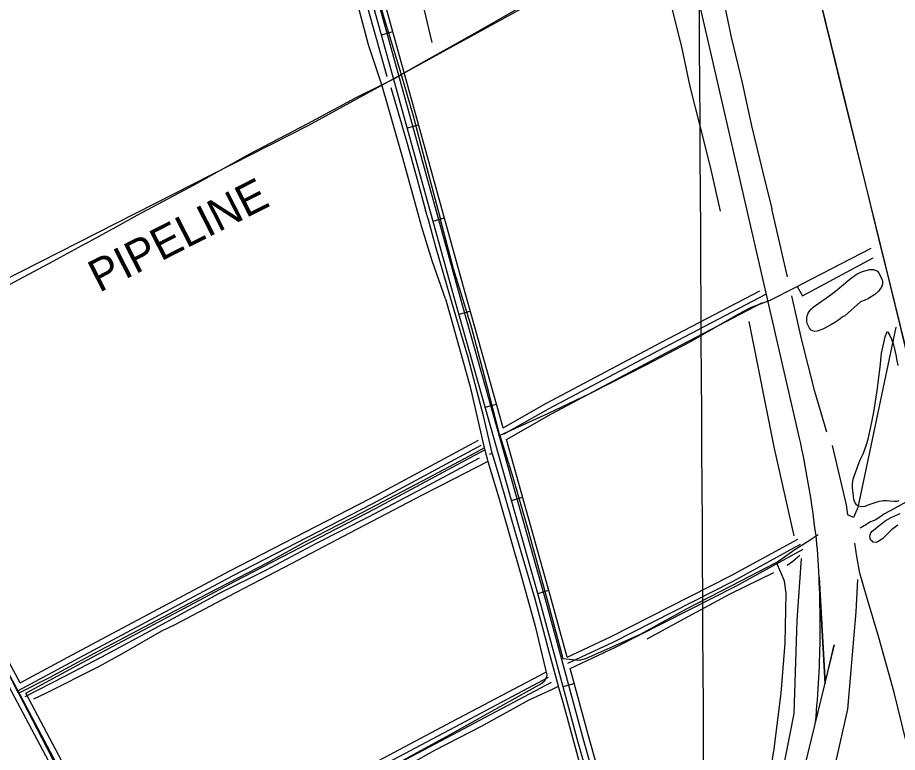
# Model space of a CAD drawing. Extents: x 3477039 to 3515015, y 546746 to 572297.
# Drawn here: x 3484689 to 3486964, y 566412 to 568313 of the extents above; entities that cross this region are included whole.
import ezdxf

# ---------------------------------------------------------------- set-up
doc = ezdxf.new("R2010")
doc.units = 0
for name, color, linetype in [('V-DTCH-CNTR', 7, 'Continuous'), ('V-GRID-MAJR', 7, 'Continuous'), ('V-RAIL-TRAK', 7, 'Continuous'), ('V-ROAD-CNTR', 7, 'Continuous'), ('V-SITE-VEGE', 7, 'Continuous'), ('V-TOPO-SHOR', 7, 'Continuous'), ('V-UTIL-IDEN', 7, 'Continuous'), ('V-UTIL-LINE', 7, 'Continuous')]:
    doc.layers.add(name, color=color, linetype=linetype)

msp = doc.modelspace()

# ---------------------------------------------------------------- linework, layer by layer
at = {"layer": 'V-DTCH-CNTR'}
for p, q in [((3485630.428, 568139.019), (3485661.847, 568154.6190000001)), ((3485816.227, 567662.634), (3485781.929, 567790.5750000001))]:
    msp.add_line(p, q, dxfattribs=at)
for points in [[(3485630.428, 568139.019), (3485596.423, 568241.759), (3485554.714, 568398.908), (3485510.833, 568547.155), (3485465.126, 568714.4890000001), (3485418.43, 568881.808), (3485377.3370000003, 569039.3), (3485345.455, 569145.878), (3485342.08, 569157.584), (3485309.318, 569271.225), (3485270.582, 569404.462), (3485231.296, 569541.164), (3485191.958, 569681.333), (3485155.059, 569824.017), (3485117.558, 569953.752), (3485115.2600000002, 569961.702), (3485074.7630000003, 570112.759), (3485029.551, 570280.101), (3485019.9982616, 570313.2061491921)], [(3485074.055938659, 570313.5285199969), (3485090.914, 570249.905), (3485131.861, 570101.831), (3485161.637, 569994.053), (3485163.362, 569987.812), (3485214.574, 569817.093), (3485249.191, 569693.705), (3485290.665, 569543.654), (3485338.531, 569364.952), (3485375.917, 569222.772), (3485386.995, 569183.481), (3485416.822, 569077.669), (3485459.789, 568927.147), (3485515.63, 568745.594), (3485552.932, 568608.863), (3485594.414, 568458.317), (3485635.325, 568312.72), (3485680.482, 568165.24)], [(3485661.847, 568154.6190000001), (3485680.482, 568165.24), (3485745.87, 568202.509), (3485872.674, 568272.87), (3486003.861, 568348.257), (3486130.663, 568418.618), (3486263.336, 568494.028), (3486359.705, 568545.082), (3486399.024, 568567.328)], [(3485680.482, 568165.24), (3485711.875, 568058.158), (3485746.679, 567922.875), (3485781.929, 567790.5750000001)], [(3484997.629, 567801.603), (3485145.231, 567880.2710000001), (3485289.344, 567959.879), (3485439.416, 568039.081), (3485563.8850000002, 568105.983), (3485630.428, 568139.019)], [(3485734.1580000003, 567770.506), (3485684.813, 567948.688), (3485647.077, 568081.448), (3485630.428, 568139.019)], [(3484865.629, 567728.803), (3484960.687, 567781.377), (3484997.629, 567801.603)], [(3485794.77, 567585.132), (3485760.532, 567683.513), (3485734.1580000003, 567770.506)], [(3484865.629, 567728.803), (3484779.767, 567681.897), (3484655.636, 567615.51), (3484576.63, 567572.188)], [(3486629.097, 567579.563), (3486704.293, 567617.232), (3486717.208, 567623.702), (3486895.447, 567716.277)], [(3486704.293, 567617.232), (3486718.156, 567593.502), (3486901.173, 567691.5210000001)], [(3485935.296, 567232.175), (3485907.881, 567339.763), (3485862.856, 567509.186), (3485816.227, 567662.634)], [(3485794.77, 567585.132), (3485808.174, 567539.475), (3485859.17, 567357.748), (3485895.257, 567200.38), (3485895.841, 567197.834), (3485902.583, 567171.409), (3485904.576, 567164.765), (3485932.898, 567070.375), (3485989.818, 566872.583), (3486026.796, 566738.537), (3486053.691, 566626.725), (3486056.8200000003, 566613.044), (3486055.79, 566605.528), (3486050.504, 566596.183), (3486042.906, 566590.158), (3485935.4020000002, 566530.283), (3485806.106, 566457.492), (3485636.112, 566364.491)], [(3486629.097, 567579.563), (3486585.616, 567562.6730000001), (3486551.066, 567545.21), (3486425.0670000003, 567472.852), (3486313.336, 567413.497), (3486169.452, 567340.41), (3486058.747, 567288.1), (3485935.296, 567232.175)], [(3485935.296, 567232.175), (3485969.2970000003, 567124.512), (3486008.145, 566989.503), (3486060.904, 566797.876), (3486096.455, 566662.438), (3486098.818, 566654.205)], [(3484691.134, 566566.0160000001), (3484771.589, 566606.456), (3484887.592, 566669.055), (3485031.974, 566744.485), (3485182.5270000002, 566824.547), (3485335.42, 566903.6410000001), (3485430.599, 566955.666), (3485581.123, 567033.378), (3485735.64, 567114.524), (3485858.737, 567180.33), (3485895.257, 567200.38)], [(3485904.576, 567164.765), (3485816.061, 567119.246), (3485735.122, 567077.873)], [(3485735.122, 567077.873), (3485586.9450000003, 566999.664), (3485564.704, 566988.637)], [(3485564.704, 566988.637), (3485410.377, 566907.68), (3485397.591, 566900.774)], [(3486440.965, 565449.836), (3486449.7120000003, 565473.252), (3486475.521, 565586.3200000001), (3486514.177, 565750.984), (3486548.8680000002, 565898.757), (3486570.333, 566041.986), (3486597.236, 566167.743), (3486626.123, 566302.414), (3486645.1410000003, 566421.773), (3486663.319, 566565.51), (3486673.802, 566695.226), (3486676.278, 566824.0970000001), (3486671.474, 566855.204), (3486665.5330000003, 566869.857), (3486660.0500000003, 566883.5650000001), (3486653.628, 566897.284), (3486650.879, 566903.432), (3486698.319, 566936.7390000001), (3486738.1380000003, 566962.138), (3486758.555, 566975.645)], [(3485397.591, 566900.774), (3485271.6720000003, 566835.002), (3485233.8000000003, 566815.225)], [(3486650.879, 566903.432), (3486533.017, 566842.74), (3486417.518, 566782.959), (3486298.6580000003, 566717.572), (3486157.2460000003, 566654.336), (3486141.202, 566650.2930000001), (3486098.818, 566654.205)], [(3484834.524, 566288.8910000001), (3484764.643, 566425.208), (3484691.971, 566564.384), (3484691.134, 566566.0160000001), (3484611.512, 566721.056), (3484567.772, 566801.081)], [(3485233.8000000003, 566815.225), (3485095.562, 566742.072), (3485060.554, 566725.553)], [(3485060.554, 566725.553), (3484957.759, 566666.0920000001), (3484898.1, 566633.87)], [(3484898.1, 566633.87), (3484761.3170000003, 566564.466), (3484729.6240000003, 566549.7880000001)]]:
    msp.add_lwpolyline(points, dxfattribs=at)
at = {"layer": 'V-GRID-MAJR'}
msp.add_spline([(3486543.572, 552138.781), (3486509.202, 558197.813), (3486474.821, 564258.778), (3486440.44, 570319.761), (3486440.429, 570321.677)], degree=3, dxfattribs=at)
at = {"layer": 'V-RAIL-TRAK'}
for points in [[(3486881.687, 567880.078), (3486858.483, 567973.17), (3486826.784, 568100.732), (3486792.089, 568242.517), (3486759.057, 568379.174), (3486722.7460000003, 568522.917), (3486691.759, 568655.642), (3486678.269, 568708.63), (3486655.467, 568798.197), (3486623.307, 568929.713), (3486591.198, 569058.061), (3486559.053, 569188.785), (3486527.278, 569321.102), (3486490.449, 569472.767), (3486455.801, 569611.382), (3486424.1210000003, 569737.752), (3486390.705, 569873.612), (3486356.4420000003, 570013.025), (3486328.9930000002, 570122.018), (3486300.178, 570242.487), (3486281.160594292, 570320.7270405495)], [(3487263.577, 566335.309), (3487241.75, 566421.7220000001), (3487220.502, 566507.544), (3487188.594, 566633.344), (3487156.2600000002, 566772.631), (3487122.085, 566904.907), (3487088.559, 567042.448), (3487057.2430000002, 567168.828), (3487026.544, 567297.545), (3486988.441, 567444.52), (3486969.466, 567524.453), (3486943.18, 567630.261), (3486915.786, 567741.357), (3486881.687, 567880.078)]]:
    msp.add_lwpolyline(points, dxfattribs=at)
at = {"layer": 'V-ROAD-CNTR'}
for p, q in [((3485629.8847021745, 568268.2404371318), (3485658.794644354, 568276.2514211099)), ((3485696.645568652, 568027.319918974), (3485725.555510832, 568035.330902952)), ((3485763.40643513, 567786.399400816), (3485792.317377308, 567794.410384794)), ((3485830.372301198, 567545.4738826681), (3485859.250243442, 567553.6008664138)), ((3485898.09616575, 567304.822363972), (3485926.974107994, 567312.94834772)), ((3485965.8200303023, 567064.169845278), (3485994.6979725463, 567072.2968290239)), ((3486033.543894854, 566823.5183265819), (3486062.421837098, 566831.645310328)), ((3486099.308763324, 566582.470808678), (3486128.261705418, 566590.3267929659))]:
    msp.add_line(p, q, dxfattribs=at)
for points in [[(3486463.731034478, 565338.246297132), (3486451.4930589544, 565363.68224626), (3486431.6880985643, 565404.7531641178), (3486138.49568495, 566438.053097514), (3486078.688804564, 566658.4646566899), (3486038.0198859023, 566807.610358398), (3485817.095327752, 567592.6537883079), (3485616.26172942, 568317.3983388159), (3485374.74221246, 569185.927601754), (3485127.3867071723, 570059.40785479), (3485058.2878453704, 570312.7433481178)], [(3486479.503002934, 565340.0612935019), (3486465.0070319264, 565370.1912332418), (3486445.764070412, 565410.0981534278), (3486152.9496560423, 566442.0640894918), (3486093.162775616, 566662.4016488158), (3486052.47585699, 566811.6153503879), (3485831.542298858, 567596.6887802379), (3485630.715700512, 568321.410330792), (3485389.184183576, 569189.9805936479), (3485141.8386782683, 570063.424846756), (3485072.7588164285, 570316.6903402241)], [(3485944.235073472, 567251.6144703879), (3485845.9892699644, 567600.7237721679), (3485645.1696716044, 568325.422322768), (3485403.6261546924, 569194.033585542), (3485156.2906493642, 570067.441838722), (3485088.280785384, 570316.7833400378)], [(3486710.89454015, 567225.4325227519), (3486478.8340042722, 568233.3885068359), (3486037.59588675, 570140.5416925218), (3485994.106973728, 570322.184329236)], [(3486710.89454015, 567225.4325227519), (3486478.8340042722, 568233.3885068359), (3486037.59588675, 570140.5416925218), (3485994.106973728, 570322.184329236)], [(3486281.2963993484, 570321.085331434), (3486969.8640222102, 567519.225935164), (3487264.1754335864, 566324.929323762)], [(3485261.6174387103, 565506.4209607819), (3485151.804658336, 565691.1675912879), (3485013.649934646, 565948.4260767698), (3484992.4669770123, 565993.858985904), (3484975.7580104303, 566037.2868990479), (3484914.272133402, 566147.826677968), (3484687.4565870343, 566575.922821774), (3484376.64920865, 567150.914671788), (3484166.0216299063, 567559.456854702), (3483812.5503368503, 568215.0615434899), (3483402.522156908, 568997.2639790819), (3483141.938678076, 569503.177967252), (3482987.7669864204, 569799.22837515)], [(3485245.3354712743, 565504.45696471), (3485138.743684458, 565683.783606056), (3485000.2339614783, 565941.7030902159), (3484978.6530046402, 565987.9899976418), (3484962.137037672, 566030.916911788), (3484901.089159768, 566140.6686922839), (3484674.2316134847, 566568.8448359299), (3484363.38423518, 567143.910685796), (3484152.752656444, 567552.4598686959), (3483799.3053633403, 568208.0195575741), (3483389.212183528, 568990.347992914), (3483387.0791877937, 568994.4889846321)], [(3484695.652570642, 566592.3057890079), (3484389.9141821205, 567157.9186577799), (3484179.290603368, 567566.453840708), (3483825.79531036, 568222.1035294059), (3483778.219405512, 568312.8623478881)], [(3485944.235073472, 567251.6144703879), (3486054.559852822, 567314.2903450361), (3486353.8572542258, 567472.86302789), (3486607.89974614, 567605.9337617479)], [(3485947.2430674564, 567236.0715014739), (3486061.777838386, 567301.139371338), (3486360.848240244, 567459.5920544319), (3486625.1147117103, 567598.0177775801)], [(3485952.6060567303, 567221.867529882), (3486068.99582395, 567287.9883976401), (3486367.839226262, 567446.3210809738), (3486614.8577322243, 567575.711822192)], [(3484689.437583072, 566572.183829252), (3484689.576582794, 566572.0018296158), (3484848.116265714, 566657.3266589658), (3485244.680472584, 566868.667236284), (3485607.140747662, 567056.1338613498), (3485887.758186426, 567206.9795596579)], [(3484695.652570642, 566592.3057890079), (3484841.0342798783, 566670.54963252), (3485237.7074865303, 566881.9482097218), (3485600.143761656, 567069.402834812), (3485880.632200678, 567220.1785332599)], [(3486109.696742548, 566658.7856560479), (3486066.9318280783, 566815.6203423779), (3485952.6060567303, 567221.867529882)], [(3486755.72445049, 566949.3560749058), (3486754.07445379, 566964.0010456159), (3486752.3464572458, 566978.6370163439), (3486750.537460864, 566993.262987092), (3486748.6494646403, 567007.87895786), (3486746.682468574, 567022.484928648), (3486744.6364726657, 567037.079899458), (3486742.5104769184, 567051.6638702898), (3486740.306481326, 567066.235841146), (3486738.022485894, 567080.794812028), (3486735.6594906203, 567095.3417829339), (3486733.218495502, 567109.8757538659), (3486730.697500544, 567124.396724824), (3486728.098505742, 567138.902695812), (3486725.420511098, 567153.395666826), (3486722.6635166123, 567167.872637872), (3486719.828522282, 567182.334608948), (3486716.91452811, 567196.7815800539), (3486713.9225340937, 567211.2125511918), (3486710.89454015, 567225.4325227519)], [(3486755.72445049, 566949.355074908), (3486754.07445379, 566964.0010456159), (3486752.3464572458, 566978.6370163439), (3486750.537460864, 566993.261987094), (3486748.6494646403, 567007.87895786), (3486746.682468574, 567022.484928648), (3486744.6364726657, 567037.079899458), (3486742.5104769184, 567051.6638702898), (3486740.306481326, 567066.235841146), (3486738.022485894, 567080.794812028), (3486735.658490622, 567095.3417829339), (3486733.218495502, 567109.8757538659), (3486730.697500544, 567124.3977248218), (3486728.098505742, 567138.902695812), (3486725.420511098, 567153.395666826), (3486722.6635166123, 567167.872637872), (3486719.828522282, 567182.334608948), (3486716.91452811, 567196.7815800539), (3486713.9225340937, 567211.2125511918), (3486710.89454015, 567225.4325227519)], [(3484709.774542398, 566565.837841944), (3484855.1982515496, 566644.103685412), (3485251.653458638, 566855.3862628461), (3485614.1377336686, 567042.864887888), (3485894.884172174, 567193.7805860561)], [(3486109.696742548, 566658.7856560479), (3486221.88051818, 566711.3525509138), (3486532.2698974, 566868.6212363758), (3486705.777550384, 566963.8690458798)], [(3486111.774738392, 566643.193687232), (3486228.454505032, 566697.867577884), (3486539.270883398, 566855.3532629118), (3486712.995535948, 566950.7200721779)], [(3486117.662726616, 566629.3867148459), (3486235.0284918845, 566684.3826048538), (3486546.2718693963, 566842.085289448), (3486720.213521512, 566937.571098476)], [(3486751.8894581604, 566490.236993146), (3486753.2404554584, 566504.628964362), (3486754.511452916, 566519.0279355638), (3486755.703450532, 566533.4339067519), (3486756.81444831, 566547.8458779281), (3486757.847446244, 566562.2648490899), (3486758.7994443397, 566576.6878202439), (3486759.6714425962, 566591.1167913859), (3486760.4644410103, 566605.550762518), (3486761.176439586, 566619.987733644), (3486761.8094383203, 566634.428704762), (3486762.362437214, 566648.8736758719), (3486762.83443627, 566663.3206469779), (3486763.227435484, 566677.770618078), (3486763.5404348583, 566692.222589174), (3486763.773434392, 566706.675560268), (3486763.9264340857, 566721.1305313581), (3486763.99943394, 566735.5855024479), (3486763.9924339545, 566750.040473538), (3486763.905434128, 566764.4954446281), (3486763.737434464, 566778.94941572), (3486763.490434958, 566793.4023868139), (3486763.163435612, 566807.8533579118), (3486762.756436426, 566822.3033290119), (3486762.2694374, 566836.750300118), (3486761.702438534, 566851.19427123), (3486761.055439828, 566865.6342423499), (3486776.527408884, 566590.3727928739), (3486759.522442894, 566894.5041846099), (3486758.6354446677, 566908.9321557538), (3486757.6694466, 566923.3551269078), (3486756.6234486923, 566937.772098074), (3486755.72445049, 566949.3560749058)], [(3486776.527408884, 566590.371792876), (3486759.522442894, 566894.5041846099), (3486758.6354446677, 566908.9321557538), (3486757.6694466, 566923.3551269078), (3486756.6234486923, 566937.772098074), (3486755.68445057, 566949.8760738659)], [(3486776.0264098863, 566588.2577971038), (3486800.333361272, 566690.8905918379), (3486723.6435146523, 566375.7222221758), (3486627.443707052, 565957.625058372), (3486536.9278880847, 565583.903805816), (3486489.22498349, 565381.343210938)], [(3484984.0569938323, 566053.224867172), (3485316.60232874, 566225.4405227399), (3485580.3998011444, 566368.7132361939), (3485812.748336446, 566492.1949892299), (3486054.201853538, 566619.9857336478)], [(3486474.624012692, 565384.781204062), (3486459.84004226, 565415.4431427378), (3486167.4036271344, 566446.0750814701), (3486117.662726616, 566629.3867148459)], [(3484976.894008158, 566034.333904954), (3484978.0260058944, 566033.208907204), (3485323.6313146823, 566212.188549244), (3485587.4987869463, 566355.4992626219), (3485819.77632239, 566478.943015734), (3486061.613838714, 566606.9367597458)], [(3484994.5549728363, 566024.876923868), (3485330.660300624, 566198.936575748), (3485594.597772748, 566342.2852890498), (3485826.8043083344, 566465.691042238), (3486069.0258238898, 566593.8877858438)], [(3484984.0569938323, 566053.224867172), (3484927.455107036, 566154.9846636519), (3484709.774542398, 566565.837841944)]]:
    msp.add_lwpolyline(points, dxfattribs=at)
at = {"layer": 'V-SITE-VEGE'}
msp.add_lwpolyline([(3486867.81, 567577.185), (3486827.318, 567541.669), (3486821.1520000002, 567537.845), (3486814.6, 567532.912), (3486801.698, 567524.3470000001), (3486791.794, 567518.152), (3486770.515, 567507.269), (3486756.163, 567501.503), (3486748.917, 567500.658), (3486740.793, 567503.908), (3486736.406, 567509.526), (3486731.517, 567519.97), (3486729.7460000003, 567527.042), (3486729.664, 567535.949), (3486730.284, 567541.323), (3486732.965, 567548.526), (3486735.245, 567552.951), (3486740.324, 567559.015), (3486745.759, 567563.591), (3486766.526, 567578.373), (3486777.179, 567585.299), (3486803.392, 567605.401), (3486813.6890000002, 567613.441), (3486840.676, 567636.504), (3486859.572, 567650.01), (3486872.995, 567655.603), (3486891.984, 567661.131), (3486901.819, 567661.204), (3486911.788, 567657.004), (3486915.9930000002, 567651.577), (3486921.799, 567640.561), (3486924.67, 567632.178), (3486924.752, 567623.458), (3486922.806, 567615.6900000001), (3486914.322, 567604.1), (3486905.327, 567596.414), (3486888.883, 567586.403), (3486877.875, 567581.15)], close=True, dxfattribs=at)
for points in [[(3486967.715, 567062.658), (3486961.762, 567061.059), (3486955.0810000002, 567060.9500000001), (3486944.151, 567062.377), (3486936.182, 567063.213), (3486927.832, 567063.125), (3486915.7490000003, 567061.04), (3486908.12, 567059.088), (3486897.133, 567055.508), (3486889.866, 567052.996), (3486879.055, 567048.6680000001), (3486871.994, 567047.638), (3486862.3680000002, 567049.424), (3486857.946, 567052.254), (3486854.115, 567057.681), (3486852.306, 567061.784), (3486851.247, 567066.248), (3486850.049, 567074.983), (3486848.843, 567082.79), (3486847.708, 567096.716), (3486847.823, 567106.549), (3486849.455, 567119.1460000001), (3486851.772, 567126.912), (3486858.487, 567145.756), (3486867.66, 567168.654), (3486874.7090000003, 567184.3420000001), (3486879.481, 567195.7880000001), (3486884.085, 567208.721), (3486887.96, 567222.777), (3486897.19, 567266.2660000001), (3486903.305, 567297.365), (3486911.755, 567353.48), (3486914.801, 567375.894), (3486918.71, 567408.502), (3486922.659, 567444.819), (3486932.059, 567487.008), (3486933.602, 567492.001), (3486935.127, 567495.507), (3486936.4790000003, 567499.9450000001), (3486938.509, 567499.179), (3486944.341, 567490.205), (3486948.501, 567481.064), (3486953.34, 567466.5380000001), (3486955.998, 567455.931), (3486959.345, 567440.678), (3486961.2600000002, 567429.895), (3486964.768, 567412.6)], [(3486964.94, 566999.797), (3486958.399, 566995.977), (3486948.29, 566988.117), (3486931.58, 566971.246), (3486925.012, 566964.827), (3486914.166, 566957.534), (3486908.389, 566955.376), (3486901.348, 566956.201), (3486899.693, 566957.334), (3486895.1010000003, 566961.468), (3486893.291, 566965.2000000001), (3486892.615, 566970.959), (3486892.846, 566974.852), (3486895.326, 566980.574), (3486898.5270000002, 566984.6190000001), (3486905.8370000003, 566990.843), (3486912.569, 566995.402), (3486923.622, 567004.5480000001), (3486931.859, 567010.944), (3486947.176, 567019.671), (3486959.109, 567024.725), (3486970.861, 567030.154)]]:
    msp.add_lwpolyline(points, dxfattribs=at)
at = {"layer": 'V-TOPO-SHOR'}
for p, q in [((3485760.4036948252, 568248.0923616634), (3485538.0917482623, 569188.3625618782)), ((3486654.346, 567751.05), (3486639.019, 567817.936)), ((3486679.865, 567642.072), (3486654.346, 567751.05)), ((3485908.5670000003, 567184.006), (3485916.237, 567186.2710000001))]:
    msp.add_line(p, q, dxfattribs=at)
for points in [[(3485042.2622067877, 570313.3389193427), (3485050.9220000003, 570280.039), (3485083.789, 570159.007), (3485115.346, 570059.113), (3485136.2970000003, 569976.77), (3485163.761, 569887.147), (3485181.126, 569814.0970000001), (3485210.154, 569718.593), (3485236.723, 569623.049), (3485259.7060000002, 569536.802), (3485287.257, 569441.275), (3485317.56, 569327.091), (3485345.681, 569226.653), (3485378.926, 569113.005), (3485413.904, 568982.656), (3485446.559, 568875.398), (3485475.899, 568759.725), (3485509.643, 568645.594), (3485544.1240000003, 568515.73), (3485584.211, 568373.159), (3485616.5330000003, 568255.563), (3485643.5870000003, 568160.519)], [(3486464.3310000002, 568573.14), (3486483.84, 568482.8640000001), (3486512.076, 568366.286), (3486533.7600000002, 568261.846), (3486562.012, 568144.289), (3486586.74, 568033.041), (3486614.992, 567915.484), (3486639.019, 567817.936)], [(3486335.463, 568513.996), (3486356.694, 568438.924), (3486381.33, 568333.553), (3486405.899, 568232.584), (3486426.506, 568134.493), (3486453.583, 568029.648), (3486479.6580000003, 567926.255), (3486505.41, 567812.087)], [(3485653.866, 568132.138), (3485673.078, 568066.9890000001), (3485697.5330000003, 567980.764), (3485721.507, 567894.04), (3485743.898, 567814.18)], [(3485769.146, 567722.436), (3485751.0640000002, 567789.934), (3485743.898, 567814.18)], [(3486383.511, 565508.765), (3486366.0640000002, 565584.2440000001), (3486339.684, 565660.2980000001), (3486309.428, 565766.505), (3486283.4760000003, 565878.31), (3486249.146, 565997.7390000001), (3486213.924, 566121.414), (3486181.4590000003, 566239.409), (3486142.715, 566383.355), (3486101.251, 566535.8), (3486087.231, 566583.01), (3486086.969, 566583.993), (3486064.262, 566668.903), (3486027.349, 566808.593), (3485977.145, 566977.609), (3485938.29, 567112.1460000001), (3485916.575, 567184.852), (3485916.237, 567186.2710000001), (3485894.178, 567279.205), (3485853.677, 567433.52), (3485810.722, 567579.397), (3485769.146, 567722.436)], [(3486780.931, 567240.523), (3486749.724, 567345.802), (3486715.596, 567482.166), (3486690.576, 567593.4890000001)], [(3486697.0294369, 566972.5320125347), (3486646.0070229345, 567198.4884172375), (3486580.4067764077, 567526.4896498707)], [(3486959.430423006, 567511.9118173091), (3486861.030053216, 567045.421175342), (3486850.096678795, 567019.9099683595), (3486835.5188462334, 567027.1988846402), (3486831.874388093, 567052.7100916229), (3486795.4298066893, 567205.7773335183)], [(3484708.071, 566557.101), (3484810.784, 566609.976), (3484906.87, 566659.169), (3485053.654, 566738.808), (3485209.431, 566823.04), (3485332.008, 566884.6190000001), (3485461.253, 566953.174), (3485596.139, 567021.192), (3485740.062, 567097.5700000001), (3485883.049, 567174.43)], [(3487058.998, 567100.855), (3487005.011, 567070.92), (3486964.274, 567047.4130000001), (3486942.967, 567035.905), (3486928.7600000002, 567028.078), (3486924.023, 567025.313), (3486907.8910000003, 567013.7440000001)], [(3486907.8910000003, 567013.7440000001), (3486894.184, 567008.261), (3486878.072, 566998.574), (3486867.646, 566992.113)], [(3487140.31, 565855.018), (3487116.943, 565947.033), (3487087.306, 566065.466), (3487048.595, 566212.236), (3487014.751, 566333.072), (3486985.029, 566444.453), (3486955.4450000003, 566567.591), (3486915.735, 566709.196), (3486883.616, 566816.841), (3486866.912, 566875.844), (3486858.485, 566918.755), (3486853.254, 566953.631)], [(3486624.140274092, 566145.2400146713), (3486697.0294369, 566513.3302868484), (3486704.31835318, 566753.8645241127), (3486715.251727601, 566914.2206822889)], [(3486711.09, 566921.53), (3486693.502, 566906.215), (3486678.326, 566896.045)], [(3486643.2830000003, 566876.706), (3486530.193, 566821.6), (3486412.2970000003, 566758.084), (3486315.704, 566705.606)], [(3486594.9846089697, 565583.9934610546), (3486722.5406438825, 566101.5065169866), (3486766.274141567, 566218.1291774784), (3486835.518846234, 566524.2636612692), (3486857.385595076, 566775.7312729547), (3486861.030053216, 566859.5538101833)], [(3485023.223, 566022.604), (3485140.149, 566083.78), (3485312.014, 566175.821), (3485478.627, 566261.335), (3485632.966, 566343.235), (3485769.357, 566419.234), (3485888.159, 566479.914), (3486011.756, 566548.067), (3486071.8340000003, 566576.049), (3486086.969, 566583.993)]]:
    msp.add_lwpolyline(points, dxfattribs=at)
at = {"layer": 'V-UTIL-LINE'}
msp.add_lwpolyline([(3483553.145, 567074.31), (3485441.599, 568034.311), (3489180.537, 570085.635), (3489289.65, 570136.554), (3489867.646, 570342.1140000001)], dxfattribs=at)

# ---------------------------------------------------------------- texts
at = {"layer": 'V-UTIL-IDEN'}
msp.add_text('PIPELINE', height=82.99983200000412, rotation=26.945740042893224, dxfattribs=at).set_placement((3484899.775905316, 567600.7033593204))

doc.saveas('drawing.dxf')
